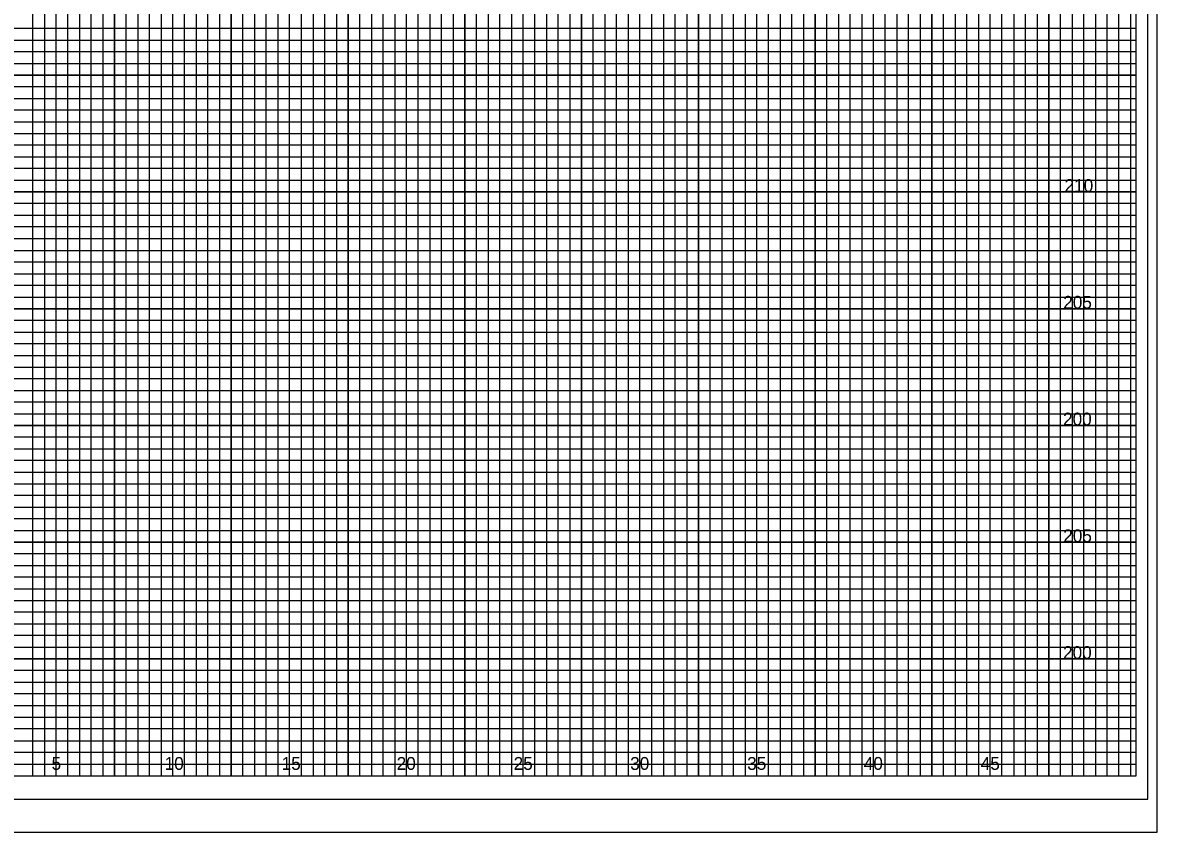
# Model space of a CAD drawing. Extents: x -4 to 103, y -2 to 209.
# Drawn here: x 54.82 to 103.4, y 139.22 to 173.9 of the extents above; entities that cross this region are included whole.
import ezdxf

# ---------------------------------------------------------------- set-up
doc = ezdxf.new("R2010")
doc.units = 0
for name, color, linetype in [('Exist XS Ground Line', 7, 'Continuous'), ('Old_Level_10', 7, 'Continuous'), ('Old_Level_16', 7, 'Continuous'), ('Old_Level_3', 7, 'Continuous'), ('Old_Level_5', 7, 'Continuous'), ('Old_Level_8', 7, 'Continuous'), ('Prop XS Finish Grade Earthwork', 7, 'Continuous'), ('Prop XS Finish Grade Pavement', 7, 'Continuous'), ('Prop XS SE Text', 7, 'Continuous')]:
    doc.layers.add(name, color=color, linetype=linetype)

msp = doc.modelspace()

# ---------------------------------------------------------------- linework, layer by layer
at = {"layer": 'Exist XS Ground Line'}
msp.add_lwpolyline([(103, 207.65), (-2.8, 207.65), (-2.8, 140.65), (103, 140.65)], close=True, dxfattribs=at)
at = {"layer": 'Old_Level_10'}
for p, q in [((56.25, 141.65), (56.25, 206.65)), ((58.75, 141.65), (58.75, 206.65)), ((61.25, 141.65), (61.25, 206.65)), ((63.75, 141.65), (63.75, 206.65)), ((66.25, 141.65), (66.25, 206.65)), ((68.75, 141.65), (68.75, 206.65)), ((71.25, 141.65), (71.25, 206.65)), ((73.75, 141.65), (73.75, 206.65)), ((91.25, 141.65), (91.25, 205.075)), ((93.75, 141.65), (93.75, 205.075)), ((96.25, 141.65), (96.25, 205.075)), ((98.75, 141.65), (98.75, 205.075)), ((101.25, 141.65), (101.25, 205.075)), ((76.25, 141.65), (76.25, 203.65)), ((78.75, 141.65), (78.75, 203.65)), ((81.25, 141.65), (81.25, 203.65)), ((83.75, 141.65), (83.75, 203.65)), ((86.25, 141.65), (86.25, 203.65)), ((88.75, 141.65), (88.75, 203.65)), ((0, 171.65), (102.5, 171.65)), ((0, 169.15), (102.5, 169.15)), ((0, 166.65), (102.5, 166.65)), ((0, 164.15), (102.5, 164.15)), ((0, 161.65), (102.5, 161.65)), ((0, 159.15), (102.5, 159.15)), ((0, 156.65), (102.5, 156.65)), ((0, 154.15), (102.5, 154.15)), ((0, 151.65), (102.5, 151.65)), ((0, 149.15), (102.5, 149.15)), ((0, 146.65), (102.5, 146.65)), ((0, 144.15), (102.5, 144.15))]:
    msp.add_line(p, q, dxfattribs=at)
at = {"layer": 'Old_Level_3'}
msp.add_line((-3.5, 139.225), (103.4, 139.225), dxfattribs=at)
at = {"layer": 'Old_Level_5'}
msp.add_lwpolyline([(103.4, 209.05), (-3.5, 209.05), (-3.5, 139.225), (103.4, 139.225)], close=True, dxfattribs=at)
at = {"layer": 'Old_Level_8'}
for points in [[(56.25, 141.65), (56.25, 206.65)], [(58.75, 206.65), (58.75, 141.65), (61.25, 141.65), (61.25, 206.65)], [(63.75, 206.65), (63.75, 141.65), (66.25, 141.65), (66.25, 206.65)], [(68.75, 206.65), (68.75, 141.65), (71.25, 141.65), (71.25, 206.65)], [(73.75, 206.65), (73.75, 141.65), (76.25, 141.65), (76.25, 203.65)], [(88.75, 203.65), (88.75, 141.65), (91.25, 141.65), (91.25, 205.075)], [(93.75, 205.075), (93.75, 141.65), (96.25, 141.65), (96.25, 205.075)], [(98.75, 205.075), (98.75, 141.65), (101.25, 141.65), (101.25, 205.075)], [(78.75, 203.65), (78.75, 141.65), (81.25, 141.65), (81.25, 203.65)], [(83.75, 203.65), (83.75, 141.65), (86.25, 141.65), (86.25, 203.65)], [(0, 169.15), (102.5, 169.15), (102.5, 171.65), (0, 171.65)], [(0, 164.15), (102.5, 164.15), (102.5, 166.65), (0, 166.65)], [(0, 159.15), (102.5, 159.15), (102.5, 161.65), (0, 161.65)], [(0, 154.15), (102.5, 154.15), (102.5, 156.65), (0, 156.65)], [(0, 149.15), (102.5, 149.15), (102.5, 151.65), (0, 151.65)], [(0, 144.15), (102.5, 144.15), (102.5, 146.65), (0, 146.65)]]:
    msp.add_lwpolyline(points, dxfattribs=at)
at = {"layer": 'Prop XS Finish Grade Earthwork'}
for points in [[(54.75, 141.65), (55.25, 141.65), (55.25, 206.65)], [(55.75, 206.65), (55.75, 141.65), (56.75, 141.65), (56.75, 206.65)], [(57.25, 206.65), (57.25, 141.65), (57.75, 141.65), (57.75, 206.65)], [(58.25, 206.65), (58.25, 141.65), (59.25, 141.65), (59.25, 206.65)], [(59.75, 206.65), (59.75, 141.65), (60.25, 141.65), (60.25, 206.65)], [(60.75, 206.65), (60.75, 141.65), (61.75, 141.65), (61.75, 206.65)], [(62.25, 206.65), (62.25, 141.65), (62.75, 141.65), (62.75, 206.65)], [(63.25, 206.65), (63.25, 141.65), (64.25, 141.65), (64.25, 206.65)], [(64.75, 206.65), (64.75, 141.65), (65.25, 141.65), (65.25, 206.65)], [(65.75, 206.65), (65.75, 141.65), (66.75, 141.65), (66.75, 206.65)], [(67.25, 206.65), (67.25, 141.65), (67.75, 141.65), (67.75, 206.65)], [(68.25, 206.65), (68.25, 141.65), (69.25, 141.65), (69.25, 206.65)], [(69.75, 206.65), (69.75, 141.65), (70.25, 141.65), (70.25, 206.65)], [(70.75, 206.65), (70.75, 141.65), (71.75, 141.65), (71.75, 206.65)], [(72.25, 206.65), (72.25, 141.65), (72.75, 141.65), (72.75, 206.65)], [(73.25, 206.65), (73.25, 141.65), (74.25, 141.65), (74.25, 203.65)], [(89.75, 203.65), (89.75, 141.65), (90.25, 141.65), (90.25, 205.075)], [(90.75, 205.075), (90.75, 141.65), (91.75, 141.65), (91.75, 205.075)], [(92.25, 205.075), (92.25, 141.65), (92.75, 141.65), (92.75, 205.075)], [(93.25, 205.075), (93.25, 141.65), (94.25, 141.65), (94.25, 205.075)], [(94.75, 205.075), (94.75, 141.65), (95.25, 141.65), (95.25, 205.075)], [(95.75, 205.075), (95.75, 141.65), (96.75, 141.65), (96.75, 205.075)], [(97.25, 205.075), (97.25, 141.65), (97.75, 141.65), (97.75, 205.075)], [(98.25, 205.075), (98.25, 141.65), (99.25, 141.65), (99.25, 205.075)], [(99.75, 205.075), (99.75, 141.65), (100.25, 141.65), (100.25, 205.075)], [(100.25, 205.075), (100.75, 205.075), (100.75, 141.65), (101.75, 141.65), (101.75, 205.075), (102.25, 205.075), (102.25, 141.65)], [(74.75, 203.65), (74.75, 141.65), (75.25, 141.65), (75.25, 203.65)], [(75.75, 203.65), (75.75, 141.65), (76.75, 141.65), (76.75, 203.65)], [(77.25, 203.65), (77.25, 141.65), (77.75, 141.65), (77.75, 203.65)], [(78.25, 203.65), (78.25, 141.65), (79.25, 141.65), (79.25, 203.65)], [(79.75, 203.65), (79.75, 141.65), (80.25, 141.65), (80.25, 203.65)], [(80.75, 203.65), (80.75, 141.65), (81.75, 141.65), (81.75, 203.65)], [(82.25, 203.65), (82.25, 141.65), (82.75, 141.65), (82.75, 203.65)], [(83.25, 203.65), (83.25, 141.65), (84.25, 141.65), (84.25, 203.65)], [(84.75, 203.65), (84.75, 141.65), (85.25, 141.65), (85.25, 203.65)], [(85.75, 203.65), (85.75, 141.65), (86.75, 141.65), (86.75, 203.65)], [(87.25, 203.65), (87.25, 141.65), (87.75, 141.65), (87.75, 203.65)], [(88.25, 203.65), (88.25, 141.65), (89.25, 141.65), (89.25, 203.65)], [(0, 173.15), (102.5, 173.15), (102.5, 173.65), (0, 173.65)], [(0, 172.15), (102.5, 172.15), (102.5, 172.65), (0, 172.65)], [(0, 170.65), (102.5, 170.65), (102.5, 171.15), (0, 171.15)], [(0, 169.65), (102.5, 169.65), (102.5, 170.15), (0, 170.15)], [(0, 168.15), (102.5, 168.15), (102.5, 168.65), (0, 168.65)], [(0, 167.15), (102.5, 167.15), (102.5, 167.65), (0, 167.65)], [(0, 165.65), (102.5, 165.65), (102.5, 166.15), (0, 166.15)], [(0, 164.65), (102.5, 164.65), (102.5, 165.15), (0, 165.15)], [(0, 163.15), (102.5, 163.15), (102.5, 163.65), (0, 163.65)], [(0, 162.15), (102.5, 162.15), (102.5, 162.65), (0, 162.65)], [(0, 160.65), (102.5, 160.65), (102.5, 161.15), (0, 161.15)], [(0, 159.65), (102.5, 159.65), (102.5, 160.15), (0, 160.15)], [(0, 158.15), (102.5, 158.15), (102.5, 158.65), (0, 158.65)], [(0, 157.15), (102.5, 157.15), (102.5, 157.65), (0, 157.65)], [(0, 155.65), (102.5, 155.65), (102.5, 156.15), (0, 156.15)], [(0, 154.65), (102.5, 154.65), (102.5, 155.15), (0, 155.15)], [(0, 153.15), (102.5, 153.15), (102.5, 153.65), (0, 153.65)], [(0, 152.15), (102.5, 152.15), (102.5, 152.65), (0, 152.65)], [(0, 150.65), (102.5, 150.65), (102.5, 151.15), (0, 151.15)], [(0, 149.65), (102.5, 149.65), (102.5, 150.15), (0, 150.15)], [(0, 148.15), (102.5, 148.15), (102.5, 148.65), (0, 148.65)], [(0, 147.15), (102.5, 147.15), (102.5, 147.65), (0, 147.65)], [(0, 145.65), (102.5, 145.65), (102.5, 146.15), (0, 146.15)], [(0, 144.65), (102.5, 144.65), (102.5, 145.15), (0, 145.15)], [(0, 143.15), (102.5, 143.15), (102.5, 143.65), (0, 143.65)], [(0, 142.15), (102.5, 142.15), (102.5, 142.65), (0, 142.65)]]:
    msp.add_lwpolyline(points, dxfattribs=at)
at = {"layer": 'Prop XS SE Text'}
msp.add_lwpolyline([(102.5, 206.65), (0, 206.65), (0, 141.65), (102.5, 141.65)], close=True, dxfattribs=at)

# ---------------------------------------------------------------- texts
at = {"layer": 'Old_Level_16'}
for s, p in [('5', (56.057, 141.9)), ('10', (60.897, 141.9)), ('15', (65.906, 141.9)), ('20', (70.831, 141.9)), ('25', (75.84, 141.9)), ('30', (80.831, 141.9)), ('35', (85.84, 141.9)), ('40', (90.831, 141.9)), ('45', (95.84, 141.9))]:
    msp.add_text(s, height=0.55, dxfattribs=at).set_placement(p)
at = {"layer": 'Prop XS Finish Grade Pavement'}
for s, p in [('210', (99.43, 166.65)), ('205', (99.372, 161.65)), ('200', (99.364, 156.65)), ('205', (99.372, 151.65)), ('200', (99.364, 146.65))]:
    msp.add_text(s, height=0.55, dxfattribs=at).set_placement(p)

doc.saveas('drawing.dxf')
